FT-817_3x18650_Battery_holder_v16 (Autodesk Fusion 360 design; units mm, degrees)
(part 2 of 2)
sketch "Sketch5" plane through (30.3495, 0, 0) normal (1, 0, 0) x axis (0, 1, 0)
  line L1 (-2.4, 0) -> (-49, 0)
  line L2 (-2.4, 1) -> (-2.4, 0)
  line L3 (-34.815, 1) -> (-40.515, 1)
  line L4 (-7.015, 4) -> (-7.015, 1)
  line L5 (-40.515, 4) -> (-34.815, 4)
  line L6 (-12.715, 1) -> (-12.715, 4)
  line L7 (-34.815, 4) -> (-34.815, 1)
  line L8 (-40.515, 1) -> (-40.515, 4)
  line L9 (-49, 1) -> (-2.4, 1)
  line L10 (-49, 0) -> (-49, 1)
  line L11 (-34.815, 2.2) -> (-40.515, 2.2)
  line L12 (-7.015, 2.2) -> (-12.715, 2.2)
  line L13 (29.985, 4) -> (29.985, 1)
  line L14 (35.685, 4) -> (35.685, 1)
  line L15 (49, 0) -> (2.4, 0)
  line L16 (49, 1) -> (49, 0)
  line L17 (2.4, 1) -> (49, 1)
  line L18 (35.685, 4) -> (35.685, 1)
  line L19 (29.985, 4) -> (35.685, 4)
  line L20 (29.985, 1) -> (29.985, 4)
  line L21 (2.4, 0) -> (2.4, 1)
  line L22 (35.685, 2.2) -> (29.985, 2.2)
  line L23 (-7.015, 1) -> (-12.715, 1)
  line L24 (-12.715, 4) -> (-7.015, 4)
  line L25 (35.685, 1) -> (29.985, 1)
  line L26 (-34.8, 1) -> (-40.5, 1)
  line L27 (-34.8, 4) -> (-34.8, 1)
  line L28 (-40.5, 4) -> (-34.8, 4)
  line L29 (-40.5, 1) -> (-40.5, 4)
  point P14 (-40.515, 2.2)
  point P15 (-34.815, 2.2)
  point P16 (-12.715, 2.2)
  point P17 (-7.015, 2.2)
  point P30 (29.985, 2.2)
  point P31 (35.685, 2.2)
  coincident L8 P14
  coincident L7 P15
  perpendicular L7 L11
  coincident L6 P16
  coincident L4 P17
  perpendicular L4 L12
  coincident L13 P30
  coincident L14 P31
  perpendicular L14 L22
  dimension "d177_1" distance L19 L22 = 1.8 (= "d190_1")
  dimension "d190_1" distance L5 L11 = 1.8
  dimension "d191_1" distance L12 L24 = 1.8 (= "d190_1")
fillet "Fillet1" radius 2.5 named "d182_1"
fillet "Fillet2" radius 1.5 named "d183_1"
extrude "Extrude10" add sketch "Sketch5" profile of L4 L5 L6 L7 L11 L12 L13 L14 L18 L19 L20 L22 L24 L28 L29 along normal blind 3 named "d192_1"
fillet "Fillet3" radius 2.25 named "d196_1"
sketch "Sketch8" plane through (0, -40.5, 0) normal (0, -1, 0) x axis (1, 0, 0)
  line L1 (30.3495, 1) -> (27.3495, 1)
  line L2 (30.3495, 2.2) -> (30.3495, 1)
  line L3 (33.3495, 2.2) -> (30.3495, 2.2)
  line L4 (33.3495, 4) -> (33.3495, 2.2)
  line L5 (27.3495, 4) -> (33.3495, 4)
  line L6 (31.5495, 2.2) -> (33.3495, 4)
  line L7 (27.3495, 1) -> (27.3495, 4)
  point P6 (33.3495, 4)
  point P8 (33.3495, 4)
  point P9 (31.5495, 2.2)
  coincident P6 P8
  coincident L3 P9
  dimension "d199_1" angle L5 L6 = 135
extrude "Extrude12" cut sketch "Sketch8" profile of L3 L4 L6 no distance stored
position "Position1"
joint_origin "JointOrigin1" OffsetX 0 named "d225_1" OffsetY 0 named "d226_1" OffsetZ 0 named "d227_1" AngleZ 0 named "d228_1"
extrude "Extrude15" add of existing geometry blind 0.5 named "d244_1"
sketch "Sketch9" plane through (0, 0, 2) normal (0, 0, 1) x axis (-1, 0, 0)
  line L1 (30.8005, -47) -> (-25.8787, -47)
  line L2 (32.3005, -10.5) -> (32.3005, -45.5)
  line L3 (30.8005, -10.5) -> (32.3005, -10.5)
  line L4 (30.8005, -6) -> (30.8005, -10.5)
  line L5 (32.8005, -6) -> (30.8005, -6)
  line L6 (32.8005, 6) -> (32.8005, -6)
  line L7 (30.8005, 6) -> (32.8005, 6)
  line L8 (30.8005, 10.5) -> (30.8005, 6)
  line L9 (32.3005, 10.5) -> (30.8005, 10.5)
  line L10 (32.3005, 45.5) -> (32.3005, 10.5)
  line L11 (28.2005, 47) -> (30.8005, 47)
  line L12 (28.2005, 46) -> (28.2005, 47)
  line L13 (29.3005, 46) -> (28.2005, 46)
  line L14 (29.3005, -46) -> (29.3005, 46)
  line L15 (-27.3495, -46) -> (29.3005, -46)
  line L16 (-27.3495, 20) -> (-27.3495, -46)
  line L17 (-27.7495, 20) -> (-27.3495, 20)
  line L18 (-27.7495, -46) -> (-27.7495, 20)
  line L19 (29.3005, -47) -> (29.3005, -46)
  line L20 (-27.7495, -46) -> (-27.3495, -46)
  arc A1 centre (-25.8787, -44.75) radius 2.25 clockwise from (-25.8787, -47) to (-27.7495, -46)
  arc A2 centre (30.8005, -45.5) radius 1.5 clockwise from (32.3005, -45.5) to (30.8005, -47)
  arc A3 centre (30.8005, 45.5) radius 1.5 clockwise from (30.8005, 47) to (32.3005, 45.5)
  point P22 (29.3005, -46)
  point P26 (29.3005, -46)
  point P27 (29.3005, -47)
  point P23 (-27.3495, -46)
  point P28 (-27.3495, -46)
  point P2 (-27.7495, -46)
  point P29 (-27.7495, -46)
  coincident P22 P26
  coincident L1 P27
  perpendicular L1 L19
  coincident P23 P28
  coincident P2 P29
extrude "Extrude13" add sketch "Sketch9" profile of A1 L1 L15 L19 L20 along normal blind 1 named "d238_1"
extrude "Extrude14" add of existing geometry blind 1 named "d240_1"
fillet "Fillet5" radius 3 named "d242_1"
fillet "Fillet7" radius 0.7 named "d246_1"
extrude "Extrude16" add of existing geometry blind 3
sketch "Sketch10" plane through (0, 0, -3) normal (0, 0, -1) x axis (1, 0, 0)
  line L1 (27.3495, 46) -> (-29.3005, 46)
  line L2 (27.3495, -46) -> (27.3495, 46)
  line L3 (-29.3005, -46) -> (27.3495, -46)
  line L4 (-29.3005, 46) -> (-29.3005, -46)
  line L5 (-30.3005, 49.5) -> (28.3495, 49.5)
  line L6 (-33.3005, -47) -> (-33.3005, 46.5)
  line L7 (28.3495, -50) -> (-30.3005, -50)
  line L8 (31.3495, -2.5) -> (31.3495, -47)
  line L9 (31.3495, 46.5) -> (31.3495, 2.5)
  line L10 (-33.3005, -47) -> (-33.3005, 46.5)
  line L11 (-30.3005, 49.5) -> (28.3495, 49.5)
  line L12 (31.3495, 46.5) -> (31.3495, 2.5)
  line L13 (31.3495, -2.5) -> (31.3495, -47)
  line L14 (28.3495, -50) -> (-30.3005, -50)
  arc A1 centre (28.3495, 46.5) radius 3 clockwise from (28.3495, 49.5) to (31.3495, 46.5)
  arc A2 centre (-30.3005, 46.5) radius 3 clockwise from (-33.3005, 46.5) to (-30.3005, 49.5)
  arc A3 centre (-30.3005, -47) radius 3 clockwise from (-30.3005, -50) to (-33.3005, -47)
  arc A4 centre (28.3495, -47) radius 3 clockwise from (31.3495, -47) to (28.3495, -50)
  arc A5 centre (31.9995, 0) radius 2.5831 clockwise from (31.3495, -2.5) to (31.3495, 2.5)
  arc A6 centre (-30.3005, 46.5) radius 3 clockwise from (-33.3005, 46.5) to (-30.3005, 49.5)
  arc A7 centre (28.3495, 46.5) radius 3 clockwise from (28.3495, 49.5) to (31.3495, 46.5)
  arc A8 centre (31.9995, 0) radius 2.5831 clockwise from (31.3495, -2.5) to (31.3495, 2.5)
  arc A9 centre (28.3495, -47) radius 3 clockwise from (31.3495, -47) to (28.3495, -50)
  arc A10 centre (-30.3005, -47) radius 3 clockwise from (-30.3005, -50) to (-33.3005, -47)
extrude "Extrude17" add sketch "Sketch10" along normal blind 2
fillet "Fillet8" radius 2.5
sketch "Sketch1" plane through (0, 0, 0) normal (0, 0, 1) x axis (1, 0, 0)
  line L1 (30.5, 48) -> (-30.5, 48)
  line L2 (30.5, -48) -> (30.5, 48)
  line L3 (-30.5, -48) -> (30.5, -48)
  line L4 (-30.5, 48) -> (-30.5, -48)
  line L5 (0, 63.5598) -> (0, 0)
  line L6 (42.8132, 0) -> (0, 0)
  line L7 (27.35, 45) -> (-27.35, 45)
  line L8 (27.35, -45) -> (27.35, 45)
  line L9 (-27.35, -45) -> (27.35, -45)
  line L10 (-27.35, 45) -> (-27.35, -45)
  point P1 (0, 0)
  point P6 (0, 0)
  point P8 (0, 0)
  point P2 (-30.5, 48)
  point P3 (30.5, 48)
  point P4 (30.5, -48)
  horizontal L1
  vertical L2
  horizontal L3
  vertical L4
  coincident P1 P6
  perpendicular L1 L5
  coincident P1 P8
  perpendicular L2 L6
  symmetric L1 L3 L6
  symmetric L2 L4 L5
  horizontal L7
  vertical L8
  horizontal L9
  vertical L10
  dimension "d128" distance P2 P3 = 61
  dimension "d129" distance P3 P4 = 96
  dimension "d130" distance L2 L8 = 3.15
  dimension "d131" distance L4 L10 = 3.15
  dimension "d132" distance L3 L9 = 3
  dimension "d133" distance L1 L7 = 3
extrude "Extrude1" new body sketch "Sketch1" profile of L1 L2 L3 L4 L7 L8 L9 L10 along normal blind 1.5 bodies "back_cap_2"
extrude "Extrude2" add sketch "Sketch1" profile of L1 L2 L3 L4 L7 L8 L9 L10 along normal blind 5.5
sketch "Sketch2" plane through (0, 0, 5.5) normal (0, 0, 1) x axis (-1, 0, 0)
  line L1 (27.35, 45) -> (-27.35, 45)
  line L2 (27.35, -45) -> (27.35, 45)
  line L3 (-27.35, -45) -> (27.35, -45)
  line L4 (-27.35, 45) -> (-27.35, -45)
  line L5 (-30.5, 48) -> (30.5, 48)
  line L6 (-30.5, -48) -> (-30.5, 48)
  line L7 (30.5, -48) -> (-30.5, -48)
  line L8 (30.5, 48) -> (30.5, -48)
  line L9 (28.35, 46) -> (-28.35, 46)
  line L10 (28.35, -46) -> (28.35, 46)
  line L11 (-28.35, -46) -> (28.35, -46)
  line L12 (-28.35, 46) -> (-28.35, -46)
  dimension "d138" = -1
extrude "Extrude3" add sketch "Sketch2" profile of L1 L2 L3 L4 L12 L11 L10 L9 along normal blind 1
fillet "Fillet1" radius 2
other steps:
base_feature "Base Feature" bodies "Body1 (1)", "Body2 (1)", "Body3 (1)"
create_component "CreateComponent1"
remove_body "RemoveBody1"
remove_body "RemoveBody2"
remove_body "RemoveBody3"
create_component "CreateComponent2"
create_component "CreateComponent3"
create_component "CreateComponent4"
create_component "CreateComponent5"
create_component "CreateComponent6"
joint_origin "JointOrigin1" OffsetX 0 OffsetY 0 OffsetZ 0 AngleZ 0
joint_origin "JointOrigin1" OffsetX 0 OffsetY 0 OffsetZ 0 AngleZ 0
create_component "CreateComponent7"
named bodies: "FT-817_Battery_holder", "Body1 (1)", "Body2 (1)", "Body3 (1)", "back_cap_2", "back_pack_part1", "back_pack_part2", "FT-817_back_cap_v2"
